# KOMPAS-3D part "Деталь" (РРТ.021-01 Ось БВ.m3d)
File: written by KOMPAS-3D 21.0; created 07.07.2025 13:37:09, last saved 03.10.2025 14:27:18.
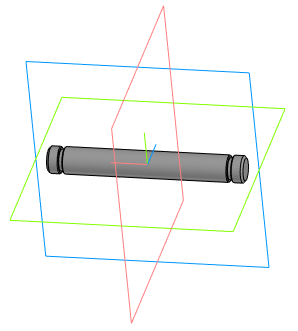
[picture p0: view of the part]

Document properties: Автор: User; Полное имя файла: C:\Users\User\Desktop\Ручной ротатор КД\Модели КД\РРТ.021-01 Ось БВ.m3d

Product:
- Part/product: Деталь
    Масса: 0.009599
    Форматы листов документа: A4

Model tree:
1. Эскиз:1
2. Элемент выдавливания:1
     Расстояние 1 = 44
3. Фаска:1  (with: Элемент выдавливания:1)
     Угол = 45; Длина 1 = 0.5; Длина 2 = 0.5
4. Эскиз:2  (with: Элемент выдавливания:1)
5. Элемент вращения:1  (with: Элемент выдавливания:1)
     Угол 1 = 360
6. Фаска:2  (with: Элемент вращения:1)
     Угол = 45; Длина 1 = 0.2; Длина 2 = 0.2

Expressions: 4.8/2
